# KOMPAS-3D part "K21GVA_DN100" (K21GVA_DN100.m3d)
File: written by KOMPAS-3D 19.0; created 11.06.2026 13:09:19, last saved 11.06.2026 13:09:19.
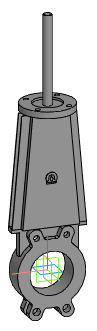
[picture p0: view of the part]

Document properties: Автор: Энергия; Полное имя файла: Z:\3.Личные\kachalov\001_3d для проектировщиков\2.5 Тип_K21GVA. Задвижка\_stp\_stp_K21GVA_DN50-DN1000_с фланцем\K21GVA_DN100.m3d

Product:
- Part/product: K21GVA_DN100

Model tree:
1. Операция без истории:1  (labels: K21GVA_DN100)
